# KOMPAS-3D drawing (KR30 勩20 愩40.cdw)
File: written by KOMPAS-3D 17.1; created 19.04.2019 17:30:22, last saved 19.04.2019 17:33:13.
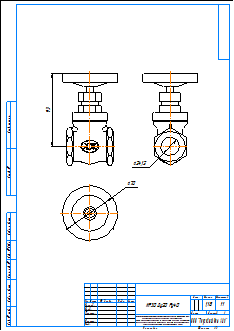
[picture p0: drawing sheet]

Sheet 1: A3, portrait

Title block, sheet 1: name: KR30 Ду20 Ру40; material: Внимание! Данный продукт является объектом авторского права ООО «Торговый Дом АДЛ». / Запрещается изменение, копирование, распространение / (в том числе путем копирования на другие сайты и ресурсы в Интернете) / или любое иное использование информации и объектов без предварительного / согласия правообладателя (ООО «Торговый Дом АДЛ»).; mass: 1,18; sheets: 1; organisation: ООО "Торговый дом АДЛ"; sheet format: A3

Views: Вид 1, Проекционный вид 2, Проекционный вид 3
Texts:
  user
Dimensions and other numbers on the sheet: 93; 24,12; 70; 1:1; 1; 1,18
